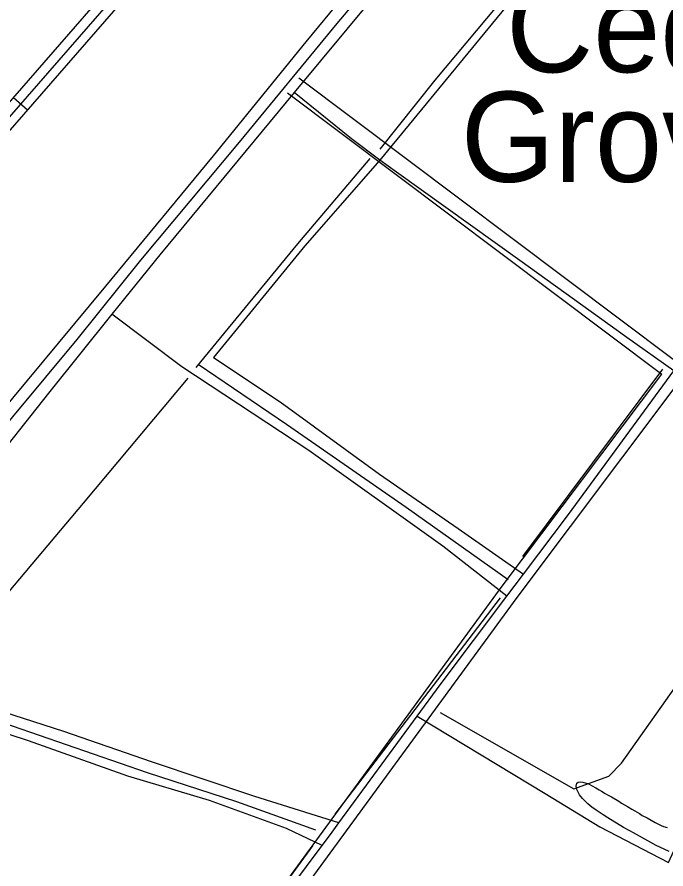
# Model space of a CAD drawing. Extents: x 3324125 to 3362000, y 600753 to 626151.
# Drawn here: x 3333814 to 3334856, y 607430 to 608800 of the extents above; entities that cross this region are included whole.
import ezdxf

# ---------------------------------------------------------------- set-up
doc = ezdxf.new("R2010")
doc.units = 0
for name, color, linetype in [('V-DTCH-CNTR', 7, 'Continuous'), ('V-ROAD-CNTR', 7, 'Continuous'), ('V-SITE-VEGE', 7, 'Continuous'), ('V-TOPO-GNAM-IDEN', 7, 'Continuous'), ('V-TOPO-SHOR', 7, 'Continuous')]:
    doc.layers.add(name, color=color, linetype=linetype)

msp = doc.modelspace()

# ---------------------------------------------------------------- linework, layer by layer
at = {"layer": 'V-DTCH-CNTR'}
for points in [[(3334510.4, 609039.4), (3334422.1, 608935.7), (3334394.4, 608901.9), (3334277.8, 608759.9), (3334129, 608576.5), (3333956, 608366.8), (3333779.5, 608155.4), (3333589.4, 607920.6), (3333557.2, 607878.3), (3333453.4, 607762.3), (3333302.2, 607588)], [(3335284.4, 608789.5), (3335066.3, 608860.8), (3334850.5, 608922.1), (3334721.6, 608965.6), (3334557.8, 608765.7), (3334396.8, 608569.8), (3334276.3, 608432.1), (3334129.4, 608252.6), (3334236.3, 608181.3), (3334396.1, 608064.9), (3334522.4, 607977.1), (3334627.4, 607904)], [(3334470.7, 608933.5), (3334259.1, 608678.4), (3334043.1, 608417.6), (3333966.1, 608321.8), (3333864.3, 608195.2), (3333695.3, 607982), (3333525.4, 607780.3), (3333511.9, 607764.3), (3333317.1, 607527.4), (3333140.5, 607309.7), (3333078.8, 607233.2), (3332948.8, 607071.9), (3332779.5, 606870.7), (3332589.3, 606644.7)], [(3333805.7, 606780.2), (3333819.2, 606820.3), (3334033.6, 607104.8), (3334304, 607467.5), (3334317.4, 607485.5), (3334331, 607504), (3334456.9, 607675.5), (3334493.8, 607725.7), (3334600.6, 607868.3), (3334627.4, 607904), (3334699.6, 608000.1), (3334868.9, 608230.9), (3334892.8, 608263.5), (3335082.6, 608518.5), (3335284.4, 608789.5), (3335426, 608739.8), (3335698.8, 608651.2), (3335817.3, 608615.7), (3335842.7, 608604)], [(3334868.9, 608230.9), (3334793.7, 608284.6), (3334621.6, 608408.4), (3334423.2, 608550.3), (3334396.8, 608569.8), (3334350.9, 608603.8), (3334259.1, 608678.4)], [(3334600.6, 607868.3), (3334498.1, 607949), (3334282.8, 608102.6), (3334078.3, 608237.4), (3333966.1, 608321.8)], [(3334456.9, 607675.5), (3334662.6, 607551.1), (3334750.3, 607497.7), (3334860.5, 607440.3), (3334895.5, 607516.3), (3335052.5, 607742.1), (3335213.5, 607976.4)], [(3334304, 607467.5), (3334246.5, 607494.8), (3334122.7, 607539.9), (3333991.9, 607578.8), (3333832.1, 607635.8), (3333702.5, 607678.1), (3333646.2, 607697.8), (3333525.4, 607780.3)], [(3334331, 607504), (3334195.9, 607546.3), (3334029.6, 607602), (3333889, 607651.1), (3333758.4, 607692.8), (3333684.9, 607715.5)]]:
    msp.add_lwpolyline(points, dxfattribs=at)
at = {"layer": 'V-ROAD-CNTR'}
for p, q in [((3334266.5, 608702), (3334867.8, 608249.7)), ((3333808, 608670.5), (3333830.6, 608650.8)), ((3334248.4, 608678.1), (3334849.6, 608225.8))]:
    msp.add_line(p, q, dxfattribs=at)
for points in [[(3331667.2, 606206.4), (3331673.7, 606210.5), (3332139.1, 606759.9), (3333317.1, 608106.6), (3334159.6, 609074.5)], [(3334170.9, 609064.6), (3333328.4, 608096.7), (3332150.5, 606750.2), (3331683.7, 606199), (3331649, 606177.1)], [(3331668.7, 606171.8), (3331693.6, 606187.5), (3332161.8, 606740.4), (3333339.7, 608086.9), (3334182.2, 609054.8)], [(3333817.8, 606843.1), (3333876.3, 606911.1), (3334203.7, 607351.3), (3334593.5, 607884.4), (3334849.6, 608225.8)], [(3333842.7, 606826), (3333899.8, 606892.3), (3334227.9, 607333.5), (3334617.6, 607866.5), (3334872.7, 608206.6)]]:
    msp.add_lwpolyline(points, dxfattribs=at)
at = {"layer": 'V-SITE-VEGE'}
msp.add_lwpolyline([(3334861.4, 607457.7), (3334846.7, 607465), (3334840.5, 607467.7), (3334831.9, 607472.4), (3334804.5, 607488), (3334798.5, 607491), (3334788.4, 607496.6), (3334763, 607511.9), (3334755.3, 607516.9), (3334744.4, 607524.5), (3334737.5, 607529.4), (3334730.9, 607534.5), (3334722.5, 607543), (3334717.6, 607549), (3334713.2, 607557.7), (3334712, 607562.8), (3334713, 607567.7), (3334715.4, 607569.2), (3334719.8, 607569.7), (3334722.9, 607569.6), (3334732.1, 607566.7), (3334743.6, 607560.3), (3334748.9, 607557.3), (3334752.7, 607554.9), (3334758.5, 607551.1), (3334762.7, 607549.1), (3334768.9, 607545.7), (3334780.7, 607538.6), (3334785.1, 607535.5), (3334794.6, 607530.1), (3334801.5, 607525.9), (3334806.2, 607523.4), (3334813.7, 607519.1), (3334818.2, 607516), (3334826, 607512), (3334839, 607504.8), (3334848.6, 607499.7), (3334852.4, 607498.1), (3334858.4, 607496.6)], dxfattribs=at)
at = {"layer": 'V-TOPO-SHOR'}
for p, q in [((3334626.5, 607932.1), (3334851.5, 608233.8)), ((3334324.8, 607518), (3334590.7, 607865.7)), ((3333798.1, 606797), (3334289, 607466.8))]:
    msp.add_line(p, q, dxfattribs=at)
for points in [[(3332142.5, 606141.3), (3332189.7, 606199.9), (3332388.8, 606439.1), (3332647.1, 606743.3), (3332885.3, 607030.3), (3332964.9, 607127.7), (3333082.9, 607271.9), (3333155.8, 607364.5), (3333227.2, 607447), (3333303.6, 607548.5), (3333478.5, 607758.5), (3333603.3, 607906), (3333755.9, 608096.6), (3333910.1, 608281.4), (3334012.5, 608409.1), (3334171, 608598.6), (3334328, 608789.7), (3334494.4, 608986.2), (3334638.5, 609160.8), (3334721.2, 609259.3), (3334803.3, 609355.5)], [(3334722.5, 608981.8), (3334618.1, 608857.4), (3334484.9, 608698.1), (3334396.7, 608587.3)], [(3334380.7, 608572.2), (3334264.2, 608435.1), (3334100.8, 608236.4)], [(3334603.1, 607894.8), (3334439.1, 608010.9), (3334246.5, 608144.7), (3334104.8, 608241.3)], [(3334088.3, 608219.2), (3333920, 608018), (3333705.9, 607764.4), (3333655.1, 607702.7)], [(3334493.5, 607681.6), (3334708.3, 607558.9), (3334764.5, 607579.3), (3334785, 607599.8), (3335091.8, 608034.4)], [(3334293.8, 607492), (3334167.1, 607537.7), (3334023.5, 607584.4), (3333806.4, 607659.7), (3333671.9, 607706.4), (3333661.6, 607710.6)]]:
    msp.add_lwpolyline(points, dxfattribs=at)

# ---------------------------------------------------------------- texts
at = {"layer": 'V-TOPO-GNAM-IDEN'}
for s, p in [('Cedar', (3334599.6, 608711.1)), ('Grove', (3334526.9, 608534.8))]:
    msp.add_text(s, height=145, rotation=359.9873, dxfattribs=at).set_placement(p)

doc.saveas('drawing.dxf')
